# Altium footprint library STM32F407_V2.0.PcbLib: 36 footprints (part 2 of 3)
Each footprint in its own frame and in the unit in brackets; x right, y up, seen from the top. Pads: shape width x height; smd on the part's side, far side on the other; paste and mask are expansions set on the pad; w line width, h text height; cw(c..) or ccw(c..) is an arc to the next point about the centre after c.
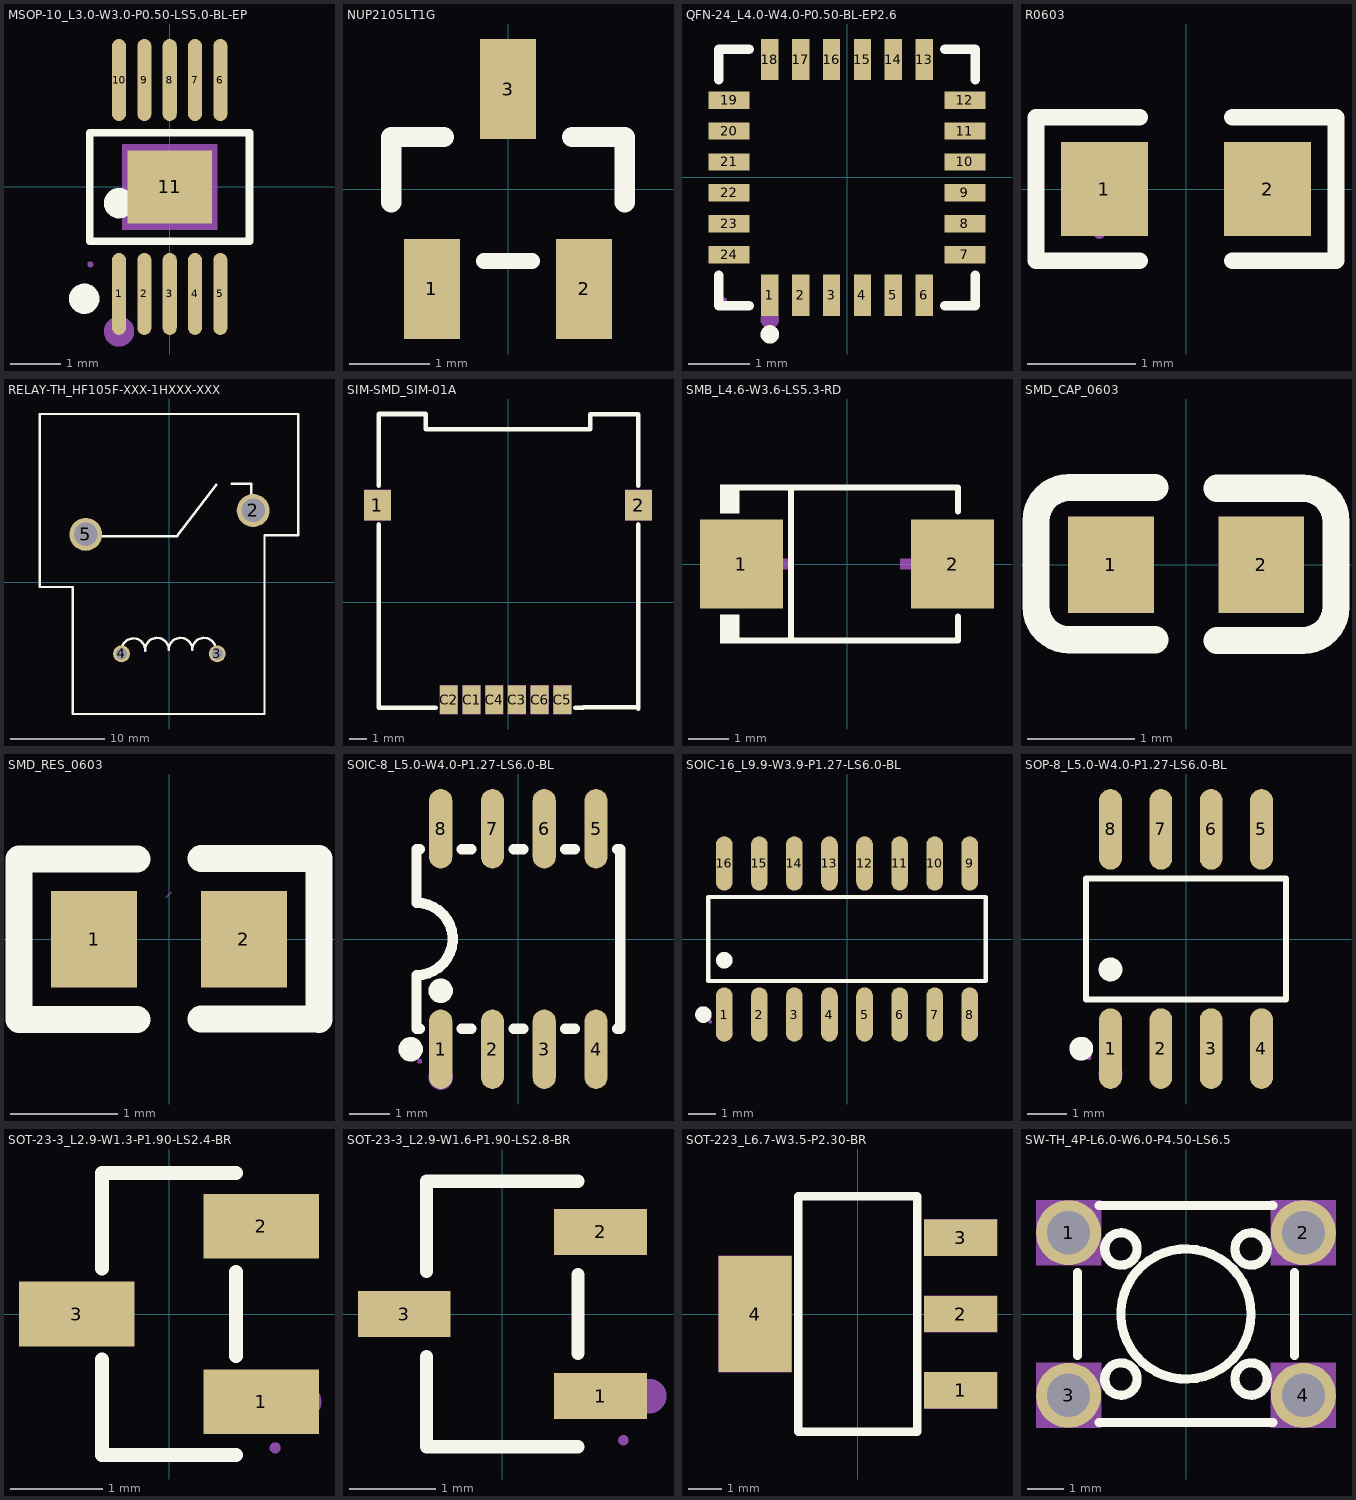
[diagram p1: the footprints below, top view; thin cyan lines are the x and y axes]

## MSOP-10_L3.0-W3.0-P0.50-LS5.0-BL-EP [mm]
pads (11):
  oval 0.28x1.62 smd: 1(-1,-2.11) 2(-0.5,-2.11) 3(0,-2.11) 4(0.5,-2.11) 5(1,-2.11) 6(1,2.11) 7(0.5,2.11) 8(0,2.11) 9(-0.5,2.11) 10(-1,2.11)
  rect 1.675x1.445 smd: 11(0,0)
Top Overlay:
  circle w0.3: c-1.687,-2.205 r0.15
  circle w0.3: c-1,-0.319 r0.15
  lines w0.152: -1.576,-1.071 1.576,-1.071 1.576,1.071 -1.576,1.071 -1.576,-1.071
Mechanical 5:
  region: -0.94,0.84 0.94,0.84 0.94,-0.84 -0.94,-0.84
  region: -1.11,-2.45 -1.11,-1.92 -0.89,-1.92 -0.89,-2.45
  pour cut-out: -1.11,-1.93 -1.11,-1.49 -0.89,-1.49 -0.89,-1.93
  region: -0.61,-2.45 -0.61,-1.92 -0.39,-1.92 -0.39,-2.45
  pour cut-out: -0.61,-1.93 -0.61,-1.49 -0.39,-1.49 -0.39,-1.93
  region: -0.11,-2.45 -0.11,-1.92 0.11,-1.92 0.11,-2.45
  pour cut-out: -0.11,-1.93 -0.11,-1.49 0.11,-1.49 0.11,-1.93
  region: 0.39,-2.45 0.39,-1.92 0.61,-1.92 0.61,-2.45
  pour cut-out: 0.39,-1.93 0.39,-1.49 0.61,-1.49 0.61,-1.93
  region: 0.89,-2.45 0.89,-1.92 1.11,-1.92 1.11,-2.45
  pour cut-out: 0.89,-1.93 0.89,-1.49 1.11,-1.49 1.11,-1.93
  region: -1.11,1.92 -1.11,2.45 -0.89,2.45 -0.89,1.92
  pour cut-out: -1.11,1.49 -1.11,1.93 -0.89,1.93 -0.89,1.49
  region: -0.61,1.92 -0.61,2.45 -0.39,2.45 -0.39,1.92
  pour cut-out: -0.61,1.49 -0.61,1.93 -0.39,1.93 -0.39,1.49
  region: -0.11,1.92 -0.11,2.45 0.11,2.45 0.11,1.92
  pour cut-out: -0.11,1.49 -0.11,1.93 0.11,1.93 0.11,1.49
  region: 0.39,1.92 0.39,2.45 0.61,2.45 0.61,1.92
  pour cut-out: 0.39,1.49 0.39,1.93 0.61,1.93 0.61,1.49
  region: 0.89,1.92 0.89,2.45 1.11,2.45 1.11,1.92
  pour cut-out: 0.89,1.49 0.89,1.93 1.11,1.93 1.11,1.49
Mechanical 6:
  circle w0.06: c-1.567,-1.528 r0.03
Mechanical 15:
  circle w0.3: c-1,-2.85 r0.15

## NUP2105LT1G [mm]
height 15.3
pads (3):
  rect 0.7x1.25 smd: 1(-0.95,-1.25) 2(0.95,-1.25) 3(0,1.25)
Top Overlay:
  lines w0.2: -0.3,-0.9 0.3,-0.9
  lines w0.254: -1.46,-0.165 -1.46,0.65 -0.8,0.65 ; 1.46,-0.165 1.46,0.65 ; 0.8,0.65 1.46,0.65 ; 0.8,0.65 1.46,0.65 ; 0.8,0.65 1.46,0.65

## QFN-24_L4.0-W4.0-P0.50-BL-EP2.6 [mm]
pads (24):
  rect 0.28x0.665 smd: 1(-1.25,-1.907) 2(-0.75,-1.907) 3(-0.25,-1.907) 4(0.25,-1.907) 5(0.75,-1.907) 6(1.25,-1.907) 13(1.25,1.907) 14(0.75,1.907) 15(0.25,1.907) 16(-0.25,1.907) 17(-0.75,1.907) 18(-1.25,1.907)
  rect 0.665x0.28 smd: 7(1.907,-1.25) 8(1.907,-0.75) 9(1.907,-0.25) 10(1.907,0.25) 11(1.907,0.75) 12(1.907,1.25) 19(-1.907,1.25) 20(-1.907,0.75) 21(-1.907,0.25) 22(-1.907,-0.25) 23(-1.907,-0.75) 24(-1.907,-1.25)
Top Overlay:
  circle w0.15: c-1.25,-2.54 r0.075
  lines w0.152: -2.076,-1.58 -2.076,-2.076 -1.58,-2.076 ; -2.076,1.58 -2.076,2.076 -1.58,2.076 ; 1.58,-2.076 2.076,-2.076 2.076,-1.58 ; 1.58,2.076 2.076,2.076 2.076,1.58
Mechanical 5:
  region: -1.6,-1.37 -1.6,-1.13 -2,-1.13 -2,-1.37
  region: -1.6,-0.87 -1.6,-0.63 -2,-0.63 -2,-0.87
  region: -1.6,-0.37 -1.6,-0.13 -2,-0.13 -2,-0.37
  region: -1.6,0.13 -1.6,0.37 -2,0.37 -2,0.13
  region: -1.6,0.63 -1.6,0.87 -2,0.87 -2,0.63
  region: -1.6,1.13 -1.6,1.37 -2,1.37 -2,1.13
  region: -1.37,2 -1.37,1.6 -1.13,1.6 -1.13,2
  region: -0.87,2 -0.87,1.6 -0.63,1.6 -0.63,2
  region: -0.37,2 -0.37,1.6 -0.13,1.6 -0.13,2
  region: 0.13,2 0.13,1.6 0.37,1.6 0.37,2
  region: 0.63,2 0.63,1.6 0.87,1.6 0.87,2
  region: 1.13,2 1.13,1.6 1.37,1.6 1.37,2
  region: 1.6,1.13 1.6,1.37 2,1.37 2,1.13
  region: 1.6,0.63 1.6,0.87 2,0.87 2,0.63
  region: 1.6,0.13 1.6,0.37 2,0.37 2,0.13
  region: 1.6,-0.37 1.6,-0.13 2,-0.13 2,-0.37
  region: 1.6,-0.87 1.6,-0.63 2,-0.63 2,-0.87
  region: 1.6,-1.37 1.6,-1.13 2,-1.13 2,-1.37
  region: 1.13,-2 1.13,-1.6 1.37,-1.6 1.37,-2
  region: 0.63,-2 0.63,-1.6 0.87,-1.6 0.87,-2
  region: 0.13,-2 0.13,-1.6 0.37,-1.6 0.37,-2
  region: -0.37,-2 -0.37,-1.6 -0.13,-1.6 -0.13,-2
  region: -0.87,-2 -0.87,-1.6 -0.63,-1.6 -0.63,-2
  region: -1.37,-2 -1.37,-1.6 -1.13,-1.6 -1.13,-2
Mechanical 6:
  circle w0.06: c-2,-2 r0.03
Mechanical 15:
  circle w0.15: c-1.25,-2.3 r0.075

## R0603 [mm]
pads (2):
  rect 0.806x0.864 smd: 1(-0.753,0) 2(0.753,0)
Top Overlay:
  lines w0.152: -0.426,-0.661 -1.385,-0.661 -1.385,0.661 -0.426,0.661 ; 0.426,-0.661 1.385,-0.661 1.385,0.661 0.426,0.661
Top Paste:
  region: 0.315,-0.138 0.315,0.138 0.589,0.432 1.092,0.432 1.156,0.368 1.156,-0.368 1.092,-0.432 0.589,-0.432
  region: -0.315,-0.138 -0.315,0.138 -0.589,0.432 -1.092,0.432 -1.156,0.368 -1.156,-0.368 -1.092,-0.432 -0.589,-0.432
Mechanical 5:
  region: -0.8,-0.4 -0.8,0.4 -0.5,0.4 -0.5,-0.4
  region: 0.8,-0.4 0.8,0.4 0.5,0.4 0.5,-0.4
Mechanical 6:
  circle w0.06: c-0.8,-0.4 r0.03

## RELAY-TH_HF105F-XXX-1HXXX-XXX [mm]
pads (4):
  round 3.5 hole 2.5: 2(8.9,7.62) 5(-8.9,5.08)
  round 1.8 hole 1.2: 3(5.08,-7.62) 4(-5.1,-7.62)
Top Overlay:
  lines w0.254: -9,4.88 0.82,4.9 5,10.38 ; -5.078,-7.399 cw(c-3.833,-7.239) -2.579,-7.299 ; -2.579,-7.2 cw(c-1.328,-7.178) -0.08,-7.101 ; -0.08,-7.2 cw(c1.171,-7.178) 2.42,-7.101 ; 2.42,-7.2 cw(c3.671,-7.178) 4.919,-7.101 ; 6.6,10.48 8.7,10.48 8.7,8.58 ; 10.1,-12.92 10.1,4.98 13.7,4.98 13.7,17.88 -13.8,17.88 -13.8,-0.52 -10.3,-0.52 -10.3,-14.02 10.1,-14.02 10.1,-12.02

## SIM-SMD_SIM-01A [mm]
pads (8):
  rect 1.5x1.7 smd: 1(-7.3,5.44) 2(7.3,5.44)
  rect 1x1.6 smd: C1(-2.041,-5.44) C2(-3.311,-5.44) C3(0.499,-5.44) C4(-0.771,-5.44) C5(3.039,-5.44) C6(1.769,-5.44)
Top Overlay:
  lines w0.254: -7.23,-5.88 -7.23,4.359 ; -7.23,6.521 -7.23,10.54 -4.6,10.54 ; -7.22,-5.88 -4.16,-5.88 -4.043,-5.88 ; -4.6,10.528 -4.6,9.68 4.6,9.68 ; 3.77,-5.88 4.21,-5.88 ; 4.22,-5.87 7.28,-5.87 ; 4.6,9.682 4.6,10.53 7.279,10.531 7.279,6.521 ; 7.279,-5.94 7.279,4.359
Mechanical 5:
  region: -3.812,-4.64 -2.812,-4.64 -2.812,-6.24 -3.812,-6.24
  region: -2.542,-4.64 -1.542,-4.64 -1.542,-6.24 -2.542,-6.24
  region: -1.272,-4.64 -0.272,-4.64 -0.272,-6.24 -1.272,-6.24
  region: -0.002,-4.64 0.998,-4.64 0.998,-6.24 -0.002,-6.24
  region: 1.268,-4.64 2.268,-4.64 2.268,-6.24 1.268,-6.24
  region: 2.538,-4.64 3.538,-4.64 3.538,-6.24 2.538,-6.24
  region: -8.05,6.29 -6.55,6.29 -6.55,4.59 -8.05,4.59
  region: 6.55,6.29 8.05,6.29 8.05,4.59 6.55,4.59

## SMB_L4.6-W3.6-LS5.3-RD [mm]
pads (2):
  rect 2.047x2.192 smd: 1(-2.609,0) 2(2.609,0)
Top Overlay:
  region: -2.668,-1.962 -2.668,-1.249 -3.125,-1.249 -3.125,-1.962
  region: -2.668,1.962 -2.668,1.249 -3.125,1.249 -3.125,1.962
  lines w0.152: -2.744,-1.886 2.744,-1.886 2.744,-1.299 ; -2.744,1.886 2.744,1.886 2.744,1.299 ; -1.382,-1.886 -1.382,1.886
Mechanical 5:
  region: 2.898,-1.015 2.898,1.015 1.758,1.015 1.758,-1.015
  region: -2.898,-1.015 -2.898,1.015 -1.758,1.015 -1.758,-1.015
Mechanical 6:
  circle w0.06: c-2.897,-1.81 r0.03
Mechanical 15:
  region: 1.989,-0.905 1.989,0.905 1.717,0.905 1.717,-0.905
  region: 2.396,-0.136 2.396,0.136 1.31,0.136 1.31,-0.136
  region: -2.396,-0.136 -2.396,0.136 -1.31,0.136 -1.31,-0.136

## SMD_CAP_0603 [mm]
height 15.3
pads (2):
  rect 0.8x0.9 smd: 1(-0.7,0) 2(0.7,0)
Top Overlay:
  lines w0.254: -0.289,-0.698 -1.089,-0.698 cw(c-1.089,-0.388) -1.399,-0.388 -1.399,0.412 cw(c-1.089,0.412) -1.089,0.722 -0.289,0.722 ; 0.287,-0.704 1.087,-0.704 ccw(c1.087,-0.394) 1.397,-0.394 1.397,0.406 ccw(c1.087,0.406) 1.087,0.716 0.287,0.716

## SMD_RES_0603 [mm]
height 15.3
pads (2):
  rect 0.8x0.9 smd: 1(-0.7,0) 2(0.7,0)
Top Overlay:
  lines w0.254: -1.401,-0.75 -0.3,-0.75 ; -1.401,0.75 -0.3,0.75 ; -1.4,-0.75 -1.4,0.75 ; 0.301,-0.745 1.401,-0.745 ; 0.301,0.755 1.401,0.755 ; 1.401,-0.75 1.401,0.75
Mechanical 15:
  lines w0.003: -0.025,0.393 0.025,0.444

## SOIC-8_L5.0-W4.0-P1.27-LS6.0-BL [mil]
pads (8):
  oval 22.38x76.78 smd: 1(-75,-106.5) 2(-25,-106.5) 3(25,-106.5) 4(75,-106.5) 5(75,106.5) 6(25,106.5) 7(-25,106.5) 8(-75,106.5)
Top Overlay:
  circle w11.81: c-75,-50 r5.91
  circle w11.81: c-104,-106.5 r5.91
  lines w10: -98.43,-35 ccw(c-98.41,0) -98.4,35 -98.42,86.61 -95.29,86.61 ; -98.42,-35 -98.42,-86.61 -95.29,-86.61 ; -54.71,-86.61 -45.29,-86.61 ; -54.71,86.61 -45.29,86.61 ; -4.71,-86.61 4.71,-86.61 ; -4.71,86.61 4.71,86.61 ; 45.29,-86.61 54.71,-86.61 ; 45.29,86.61 54.71,86.61 ; 95.29,-86.61 98.42,-86.61 98.42,86.61 95.29,86.61
Mechanical 5:
  region: -82.99,-118.11 -82.99,-92.13 -67.01,-92.13 -67.01,-118.11
  pour cut-out: -82.99,-92.52 -82.99,-75.59 -67.01,-75.59 -67.01,-92.52
  region: -32.99,-118.11 -32.99,-92.13 -17.01,-92.13 -17.01,-118.11
  pour cut-out: -32.99,-92.52 -32.99,-75.59 -17.01,-75.59 -17.01,-92.52
  region: 17.01,-118.11 17.01,-92.13 32.99,-92.13 32.99,-118.11
  pour cut-out: 17.01,-92.52 17.01,-75.59 32.99,-75.59 32.99,-92.52
  region: 67.01,-118.11 67.01,-92.13 82.99,-92.13 82.99,-118.11
  pour cut-out: 67.01,-92.52 67.01,-75.59 82.99,-75.59 82.99,-92.52
  region: -82.99,118.11 -82.99,92.13 -67.01,92.13 -67.01,118.11
  pour cut-out: -82.99,92.52 -82.99,75.59 -67.01,75.59 -67.01,92.52
  region: -32.99,118.11 -32.99,92.13 -17.01,92.13 -17.01,118.11
  pour cut-out: -32.99,92.52 -32.99,75.59 -17.01,75.59 -17.01,92.52
  region: 17.01,118.11 17.01,92.13 32.99,92.13 32.99,118.11
  pour cut-out: 17.01,92.52 17.01,75.59 32.99,75.59 32.99,92.52
  region: 67.01,118.11 67.01,92.13 82.99,92.13 82.99,118.11
  pour cut-out: 67.01,92.52 67.01,75.59 82.99,75.59 82.99,92.52
Mechanical 6:
  circle w2.36: c-95.28,-118.11 r1.18
Mechanical 15:
  circle w11.81: c-75,-133.86 r5.91

## SOIC-16_L9.9-W3.9-P1.27-LS6.0-BL [mm]
pads (16):
  oval 0.602x1.971 smd: 1(-4.445,-2.736) 2(-3.175,-2.736) 3(-1.905,-2.736) 4(-0.635,-2.736) 5(0.635,-2.736) 6(1.905,-2.736) 7(3.175,-2.736) 8(4.445,-2.736) 9(4.445,2.736) 10(3.175,2.736) 11(1.905,2.736) 12(0.635,2.736) 13(-0.635,2.736) 14(-1.905,2.736) 15(-3.175,2.736) 16(-4.445,2.736)
Top Overlay:
  circle w0.3: c-4.445,-0.769 r0.15
  circle w0.3: c-5.198,-2.736 r0.15
  lines w0.152: -5.026,-1.521 -5.026,1.521 5.026,1.521 5.026,-1.521 -5.026,-1.521
Mechanical 5:
  region: -4.66,-3 -4.66,-2.3 -4.23,-2.3 -4.23,-3
  pour cut-out: -4.66,-2.31 -4.66,-1.94 -4.23,-1.94 -4.23,-2.31
  region: -3.39,-3 -3.39,-2.3 -2.96,-2.3 -2.96,-3
  pour cut-out: -3.39,-2.31 -3.39,-1.94 -2.96,-1.94 -2.96,-2.31
  region: -2.12,-3 -2.12,-2.3 -1.69,-2.3 -1.69,-3
  pour cut-out: -2.12,-2.31 -2.12,-1.94 -1.69,-1.94 -1.69,-2.31
  region: -0.85,-3 -0.85,-2.3 -0.42,-2.3 -0.42,-3
  pour cut-out: -0.85,-2.31 -0.85,-1.94 -0.42,-1.94 -0.42,-2.31
  region: 0.42,-3 0.42,-2.3 0.85,-2.3 0.85,-3
  pour cut-out: 0.42,-2.31 0.42,-1.94 0.85,-1.94 0.85,-2.31
  region: 1.69,-3 1.69,-2.3 2.12,-2.3 2.12,-3
  pour cut-out: 1.69,-2.31 1.69,-1.94 2.12,-1.94 2.12,-2.31
  region: 2.96,-3 2.96,-2.3 3.39,-2.3 3.39,-3
  pour cut-out: 2.96,-2.31 2.96,-1.94 3.39,-1.94 3.39,-2.31
  region: 4.23,-3 4.23,-2.3 4.66,-2.3 4.66,-3
  pour cut-out: 4.23,-2.31 4.23,-1.94 4.66,-1.94 4.66,-2.31
  region: -4.66,3 -4.66,2.3 -4.23,2.3 -4.23,3
  pour cut-out: -4.66,2.31 -4.66,1.94 -4.23,1.94 -4.23,2.31
  region: -3.39,3 -3.39,2.3 -2.96,2.3 -2.96,3
  pour cut-out: -3.39,2.31 -3.39,1.94 -2.96,1.94 -2.96,2.31
  region: -2.12,3 -2.12,2.3 -1.69,2.3 -1.69,3
  pour cut-out: -2.12,2.31 -2.12,1.94 -1.69,1.94 -1.69,2.31
  region: -0.85,3 -0.85,2.3 -0.42,2.3 -0.42,3
  pour cut-out: -0.85,2.31 -0.85,1.94 -0.42,1.94 -0.42,2.31
  region: 0.42,3 0.42,2.3 0.85,2.3 0.85,3
  pour cut-out: 0.42,2.31 0.42,1.94 0.85,1.94 0.85,2.31
  region: 1.69,3 1.69,2.3 2.12,2.3 2.12,3
  pour cut-out: 1.69,2.31 1.69,1.94 2.12,1.94 2.12,2.31
  region: 2.96,3 2.96,2.3 3.39,2.3 3.39,3
  pour cut-out: 2.96,2.31 2.96,1.94 3.39,1.94 3.39,2.31
  region: 4.23,3 4.23,2.3 4.66,2.3 4.66,3
  pour cut-out: 4.23,2.31 4.23,1.94 4.66,1.94 4.66,2.31
Mechanical 6:
  circle w0.06: c-4.95,-3 r0.03
Mechanical 15:
  circle w0.3: c-4.445,-3.4 r0.15

## SOP-8_L5.0-W4.0-P1.27-LS6.0-BL [mm]
pads (8):
  oval 0.574x2.036 smd: 1(-1.905,-2.768) 2(-0.635,-2.768) 3(0.635,-2.768) 4(1.905,-2.768) 5(1.905,2.768) 6(0.635,2.768) 7(-0.635,2.768) 8(-1.905,2.768)
Top Overlay:
  circle w0.3: c-1.905,-0.769 r0.15
  circle w0.3: c-2.644,-2.768 r0.15
  lines w0.152: -2.526,-1.521 -2.526,1.521 2.526,1.521 2.526,-1.521 -2.526,-1.521
Mechanical 5:
  region: -2.11,-2.998 -2.11,-2.163 -1.7,-2.163 -1.7,-2.998
  pour cut-out: -2.11,-2.172 -2.11,-1.94 -1.7,-1.94 -1.7,-2.172
  region: -0.84,-2.998 -0.84,-2.163 -0.43,-2.163 -0.43,-2.998
  pour cut-out: -0.84,-2.172 -0.84,-1.94 -0.43,-1.94 -0.43,-2.172
  region: 0.43,-2.998 0.43,-2.163 0.84,-2.163 0.84,-2.998
  pour cut-out: 0.43,-2.172 0.43,-1.94 0.84,-1.94 0.84,-2.172
  region: 1.7,-2.998 1.7,-2.163 2.11,-2.163 2.11,-2.998
  pour cut-out: 1.7,-2.172 1.7,-1.94 2.11,-1.94 2.11,-2.172
  region: -2.11,2.998 -2.11,2.163 -1.7,2.163 -1.7,2.998
  pour cut-out: -2.11,2.172 -2.11,1.94 -1.7,1.94 -1.7,2.172
  region: -0.84,2.998 -0.84,2.163 -0.43,2.163 -0.43,2.998
  pour cut-out: -0.84,2.172 -0.84,1.94 -0.43,1.94 -0.43,2.172
  region: 0.43,2.998 0.43,2.163 0.84,2.163 0.84,2.998
  pour cut-out: 0.43,2.172 0.43,1.94 0.84,1.94 0.84,2.172
  region: 1.7,2.998 1.7,2.163 2.11,2.163 2.11,2.998
  pour cut-out: 1.7,2.172 1.7,1.94 2.11,1.94 2.11,2.172
Mechanical 6:
  circle w0.06: c-2.45,-2.997 r0.03
Mechanical 15:
  circle w0.3: c-1.905,-3.398 r0.15

## SOT-23-3_L2.9-W1.3-P1.90-LS2.4-BR [mm]
pads (3):
  rect 1.25x0.7 smd: 1(1,-0.95) 2(1,0.95) 3(-1,0)
Top Overlay:
  lines w0.152: -0.726,-0.495 -0.726,-1.526 0.726,-1.526 ; -0.726,0.495 -0.726,1.526 0.726,1.526 ; 0.726,-0.455 0.726,0.455
Mechanical 5:
  region: 0.85,-1.165 0.85,-0.735 1.15,-0.735 1.15,-1.165
  pour cut-out: 0.64,-1.165 0.64,-0.735 0.86,-0.735 0.86,-1.165
  region: 0.85,0.735 0.85,1.165 1.15,1.165 1.15,0.735
  pour cut-out: 0.64,0.735 0.64,1.165 0.86,1.165 0.86,0.735
  region: -0.85,-0.215 -0.85,0.215 -1.15,0.215 -1.15,-0.215
  pour cut-out: -0.86,-0.215 -0.86,0.215 -0.64,0.215 -0.64,-0.215
Mechanical 6:
  circle w0.06: c1.15,-1.45 r0.03
Mechanical 15:
  circle w0.2: c1.45,-0.95 r0.1

## SOT-23-3_L2.9-W1.6-P1.90-LS2.8-BR [mm]
pads (3):
  rect 1.07x0.532 smd: 1(1.135,-0.95) 2(1.135,0.95) 3(-1.135,0)
Top Overlay:
  lines w0.152: -0.876,-0.495 -0.876,-1.536 0.876,-1.536 ; -0.876,0.495 -0.876,1.536 0.876,1.536 ; 0.876,-0.455 0.876,0.455
Mechanical 5:
  region: 0.95,-1.15 0.95,-0.75 1.4,-0.75 1.4,-1.15
  pour cut-out: 0.79,-1.15 0.79,-0.75 0.96,-0.75 0.96,-1.15
  region: 0.95,0.75 0.95,1.15 1.4,1.15 1.4,0.75
  pour cut-out: 0.79,0.75 0.79,1.15 0.96,1.15 0.96,0.75
  region: -0.95,-0.2 -0.95,0.2 -1.4,0.2 -1.4,-0.2
  pour cut-out: -0.96,-0.2 -0.96,0.2 -0.79,0.2 -0.79,-0.2
Mechanical 6:
  circle w0.06: c1.4,-1.46 r0.03
Mechanical 15:
  circle w0.2: c1.7,-0.95 r0.1

## SOT-223_L6.7-W3.5-P2.30-BR [mm]
pads (4):
  rect 2.2x1.1 smd: 1(3.099,-2.3) 2(3.099,0) 3(3.099,2.3)
  rect 2.2x3.5 smd: 4(-3.099,0)
Top Overlay:
  lines w0.254: -1.8,-3.55 -1.8,3.55 1.8,3.55 1.8,-3.55 -1.8,-3.55
Mechanical 5:
  region: 1.999,-1.75 4.199,-1.75 4.199,-2.85 1.999,-2.85
  region: 1.999,0.55 4.199,0.55 4.199,-0.55 1.999,-0.55
  region: 1.999,2.85 4.199,2.85 4.199,1.75 1.999,1.75
  region: -4.199,1.75 -1.999,1.75 -1.999,-1.75 -4.199,-1.75

## SW-TH_4P-L6.0-W6.0-P4.50-LS6.5 [mm]
pads (4):
  round 1.8 hole 1.2: 1(-3.25,2.25) 2(3.25,2.25) 3(-3.25,-2.25) 4(3.25,-2.25)
Top Overlay:
  circle w0.254: c0,0 r1.8
  circle w0.254: c1.8,1.8 r0.447
  circle w0.254: c-1.8,1.8 r0.447
  circle w0.254: c-1.8,-1.8 r0.447
  circle w0.254: c1.8,-1.8 r0.447
  lines w0.254: -3,-1.147 -3,1.147 ; -2.404,-3 2.404,-3 ; -2.404,3 2.404,3 ; 3,-1.147 3,1.147
Mechanical 5:
  region: -4.15,3.15 -2.35,3.15 -2.35,1.35 -4.15,1.35
  region: 2.35,3.15 4.15,3.15 4.15,1.35 2.35,1.35
  region: -4.15,-1.35 -2.35,-1.35 -2.35,-3.15 -4.15,-3.15
  region: 2.35,-1.35 4.15,-1.35 4.15,-3.15 2.35,-3.15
